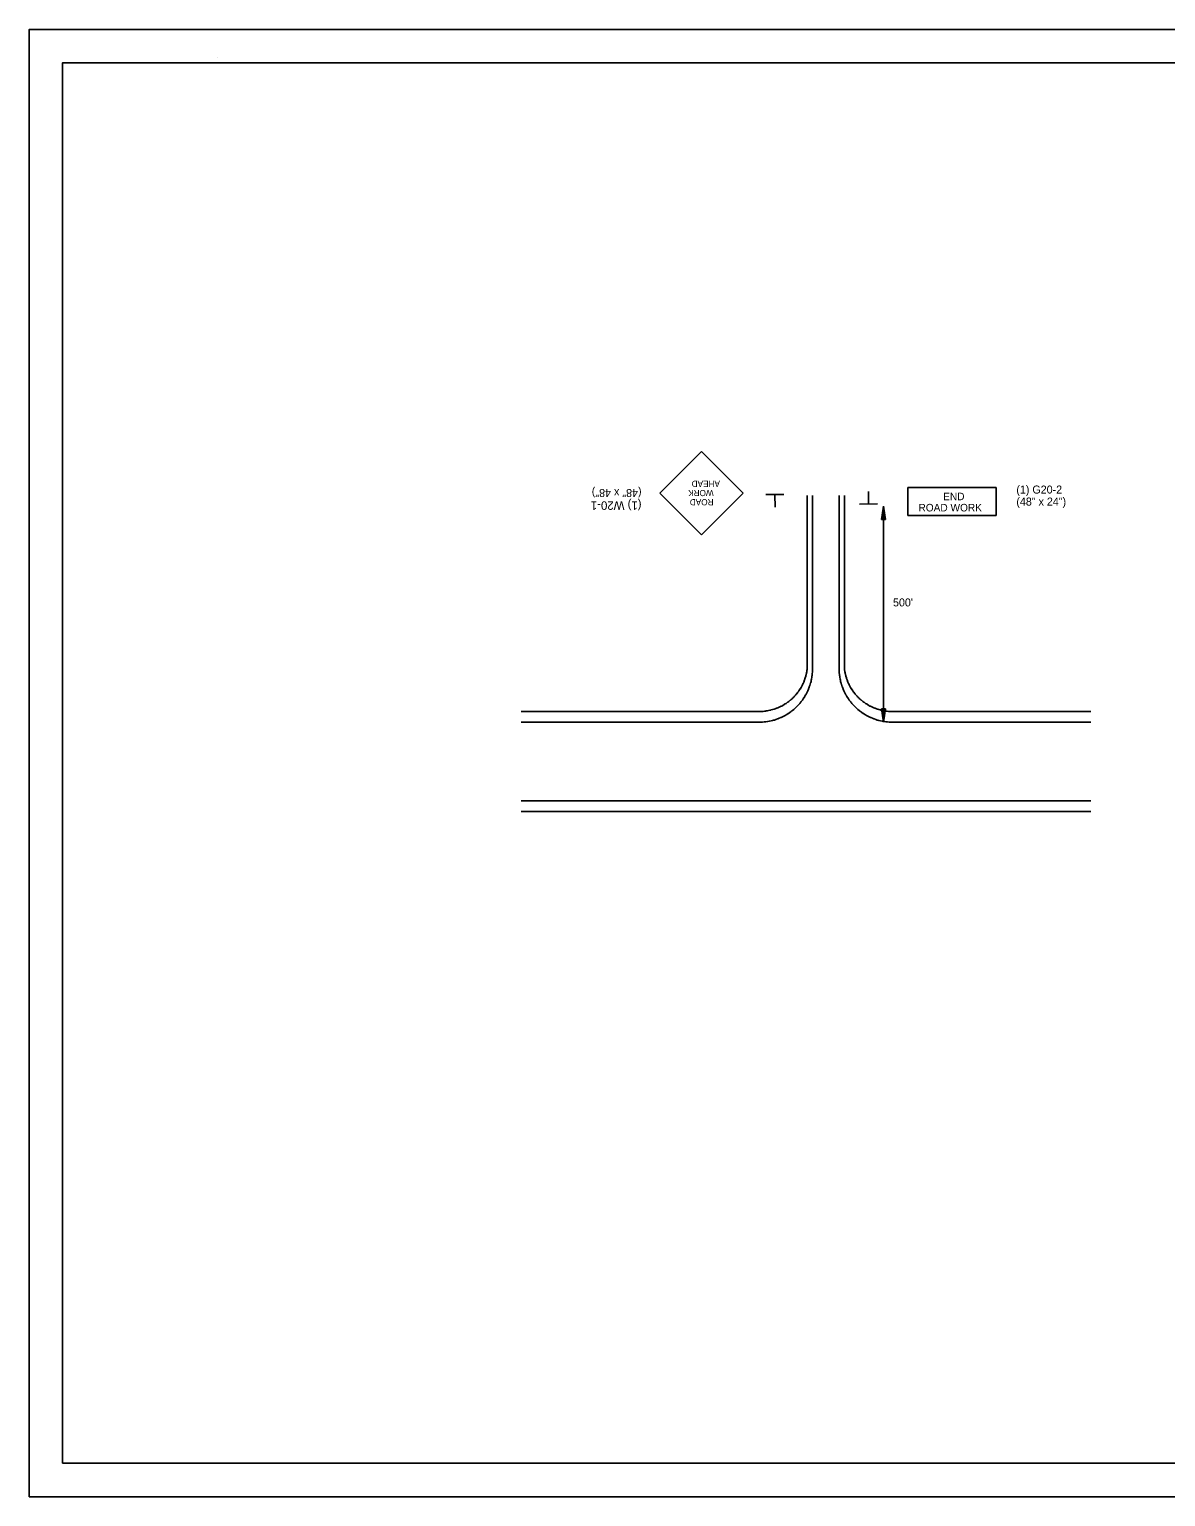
# Model space of a CAD drawing. Extents: x 32485 to 39285, y 55121 to 58033.
# Drawn here: x 32485 to 33337, y 56764 to 57864 of the extents above; entities that cross this region are included whole.
import ezdxf

# ---------------------------------------------------------------- set-up
doc = ezdxf.new("R2010")
doc.units = 0
doc.layers.add('Default', color=7, linetype='Continuous')
doc.layers.add('R_Border Notes', color=7, linetype='Continuous')

msp = doc.modelspace()

# ---------------------------------------------------------------- linework, layer by layer
at = {"layer": 'Default'}
for p, q in [((32957.9, 57516.2), (32989.2, 57547.4)), ((32989.2, 57547.4), (33020.5, 57516.2)), ((33210.2, 57520.4), (33143.8, 57520.4)), ((33143.8, 57499.5), (33143.8, 57520.4)), ((33210.2, 57499.5), (33210.2, 57520.4)), ((32957.9, 57516.2), (32989.2, 57484.9)), ((32989.2, 57484.9), (33020.5, 57516.2)), ((33037.5, 57515.1), (33051, 57515.3)), ((33044.2, 57515), (33044.4, 57505.8)), ((33068.4, 57476), (33068.4, 57514.5)), ((33072.4, 57476), (33072.4, 57514.5)), ((33092.4, 57476), (33092.4, 57514.5)), ((33096.4, 57476), (33096.4, 57514.5)), ((33121.1, 57508.1), (33107.6, 57508)), ((33114.3, 57508.3), (33114.3, 57517.5)), ((33124.2, 57496.4), (33125.7, 57506.4)), ((33124.5, 57496.4), (33125.7, 57504.7)), ((33124.7, 57496.4), (33125.7, 57503)), ((33125, 57496.4), (33125.7, 57501.4)), ((33125.2, 57496.4), (33125.7, 57499.7)), ((33125.5, 57496.4), (33125.7, 57498)), ((33125.7, 57506.4), (33125.7, 57344.5)), ((33127.2, 57496.4), (33125.7, 57506.4)), ((33127, 57496.4), (33125.7, 57504.7)), ((33126.7, 57496.4), (33125.7, 57503)), ((33126.4, 57496.4), (33125.7, 57501.4)), ((33126.2, 57496.4), (33125.7, 57499.7)), ((33125.9, 57496.4), (33125.7, 57498)), ((33210.2, 57499.5), (33143.8, 57499.5)), ((33124.2, 57496.4), (33127.2, 57496.4)), ((33124.2, 57354.5), (33125.7, 57344.5)), ((33124.2, 57354.5), (33127.2, 57354.5)), ((33124.5, 57354.5), (33125.7, 57346.2)), ((33124.7, 57354.5), (33125.7, 57347.9)), ((33125, 57354.5), (33125.7, 57349.5)), ((33125.2, 57354.5), (33125.7, 57351.2)), ((33125.5, 57354.5), (33125.7, 57352.9)), ((33127.2, 57354.5), (33125.7, 57344.5)), ((33126.2, 57354.5), (33125.7, 57351.2)), ((33126.7, 57354.5), (33125.7, 57347.9)), ((33127, 57354.5), (33125.7, 57346.2)), ((33126.4, 57354.5), (33125.7, 57349.5)), ((33125.9, 57354.5), (33125.7, 57352.9))]:
    msp.add_line(p, q, dxfattribs=at)
msp.add_lwpolyline([(32485, 57863.9), (32485, 56763.9), (34185, 56763.9), (34185, 57863.9)], close=True, dxfattribs=at)
for points in [[(33032.4, 57344.5), (33033.7, 57344.5), (33035, 57344.6), (33036.2, 57344.7), (33037.5, 57344.8), (33038.7, 57345), (33038.8, 57345), (33040, 57345.2), (33041.3, 57345.5), (33042.5, 57345.8), (33043.2, 57346), (33043.8, 57346.1), (33045, 57346.5), (33046.2, 57347), (33046.3, 57347), (33047.4, 57347.4), (33048.6, 57347.9), (33048.8, 57348), (33049.8, 57348.5), (33050.8, 57349), (33050.9, 57349), (33052, 57349.6), (33052.6, 57350), (33053.1, 57350.3), (33054.2, 57351), (33054.3, 57351), (33055.3, 57351.7), (33055.7, 57352), (33056.3, 57352.4), (33057, 57353), (33057.3, 57353.2), (33058.3, 57354), (33058.3, 57354), (33059.3, 57354.9), (33059.4, 57355), (33060.2, 57355.8), (33060.5, 57356), (33060.7, 57356.2), (33061.1, 57356.7), (33061.4, 57357), (33062, 57357.6), (33062.4, 57358), (33062.9, 57358.6), (33063.2, 57359), (33063.7, 57359.6), (33064, 57360), (33064.5, 57360.6), (33064.8, 57361), (33065.2, 57361.6), (33065.5, 57362), (33065.9, 57362.7), (33066.1, 57363), (33066.6, 57363.8), (33066.7, 57364), (33067, 57364.5), (33067.2, 57364.9), (33067.3, 57365), (33067.9, 57366), (33067.9, 57366), (33068.4, 57367), (33068.4, 57367.1), (33068.8, 57368), (33069, 57368.3), (33069.3, 57369), (33069.5, 57369.5), (33069.7, 57370), (33069.9, 57370.7), (33070, 57371), (33070.4, 57371.9), (33070.4, 57372), (33070.7, 57373), (33070.7, 57373.1), (33071, 57374), (33071.1, 57374.3), (33071.3, 57375), (33071.4, 57375.6), (33071.5, 57376), (33071.7, 57376.8), (33071.7, 57377), (33071.9, 57378), (33071.9, 57378.1), (33072, 57379), (33072.1, 57379.4), (33072.1, 57380), (33072.2, 57380.7), (33072.2, 57381), (33072.3, 57381.9), (33072.3, 57382), (33072.4, 57383), (33072.4, 57383.2), (33072.4, 57384), (33072.4, 57384.5), (33072.4, 57385), (33072.4, 57386), (33072.4, 57387), (33072.4, 57388), (33072.4, 57389), (33072.4, 57390), (33072.4, 57391), (33072.4, 57392), (33072.4, 57393), (33072.4, 57394), (33072.4, 57395), (33072.4, 57396), (33072.4, 57397), (33072.4, 57398), (33072.4, 57399), (33072.4, 57400), (33072.4, 57401), (33072.4, 57402), (33072.4, 57403), (33072.4, 57404), (33072.4, 57405), (33072.4, 57406), (33072.4, 57407), (33072.4, 57408), (33072.4, 57409), (33072.4, 57410), (33072.4, 57411), (33072.4, 57412), (33072.4, 57413), (33072.4, 57414), (33072.4, 57415), (33072.4, 57416), (33072.4, 57417), (33072.4, 57418), (33072.4, 57419), (33072.4, 57420), (33072.4, 57421), (33072.4, 57422), (33072.4, 57423), (33072.4, 57424), (33072.4, 57425), (33072.4, 57426), (33072.4, 57427), (33072.4, 57428), (33072.4, 57429), (33072.4, 57430), (33072.4, 57431), (33072.4, 57432), (33072.4, 57433), (33072.4, 57434), (33072.4, 57435), (33072.4, 57436), (33072.4, 57437), (33072.4, 57438), (33072.4, 57439), (33072.4, 57440), (33072.4, 57441), (33072.4, 57442), (33072.4, 57443), (33072.4, 57444), (33072.4, 57445), (33072.4, 57446), (33072.4, 57447), (33072.4, 57448), (33072.4, 57449), (33072.4, 57450), (33072.4, 57451), (33072.4, 57452), (33072.4, 57453), (33072.4, 57454), (33072.4, 57455), (33072.4, 57456), (33072.4, 57457), (33072.4, 57458), (33072.4, 57459), (33072.4, 57460), (33072.4, 57461), (33072.4, 57462), (33072.4, 57463), (33072.4, 57464), (33072.4, 57464.5), (33072.4, 57465), (33072.4, 57466), (33072.4, 57467), (33072.4, 57468), (33072.4, 57469), (33072.4, 57470), (33072.4, 57471), (33072.4, 57472), (33072.4, 57473), (33072.4, 57473.7), (33072.4, 57474), (33072.4, 57475), (33072.4, 57476)], [(33032.4, 57352.5), (33033.4, 57352.5), (33034.4, 57352.5), (33035.5, 57352.6), (33036.5, 57352.7), (33037.4, 57352.8), (33037.5, 57352.9), (33038.5, 57353), (33039.5, 57353.2), (33040.5, 57353.4), (33041.1, 57353.5), (33041.5, 57353.7), (33042.5, 57353.9), (33043.5, 57354.2), (33043.6, 57354.3), (33044.5, 57354.6), (33045.5, 57354.9), (33045.6, 57355), (33046.5, 57355.3), (33047.3, 57355.7), (33047.4, 57355.7), (33048.4, 57356.2), (33048.9, 57356.4), (33049.3, 57356.6), (33050.2, 57357.1), (33050.2, 57357.1), (33051.1, 57357.7), (33051.5, 57357.9), (33052, 57358.2), (33052.6, 57358.6), (33052.9, 57358.8), (33053.7, 57359.4), (33053.8, 57359.4), (33054.6, 57360), (33054.7, 57360.1), (33055.4, 57360.7), (33055.7, 57360.9), (33055.9, 57361), (33056.3, 57361.4), (33056.5, 57361.6), (33057.1, 57362.1), (33057.4, 57362.4), (33057.8, 57362.8), (33058.2, 57363.2), (33058.6, 57363.6), (33058.9, 57363.9), (33059.3, 57364.4), (33059.6, 57364.7), (33060, 57365.2), (33060.3, 57365.5), (33060.7, 57366), (33060.9, 57366.3), (33061.4, 57366.9), (33061.5, 57367.1), (33061.8, 57367.5), (33062.1, 57367.8), (33062.1, 57367.9), (33062.7, 57368.7), (33062.7, 57368.7), (33063.2, 57369.5), (33063.3, 57369.6), (33063.7, 57370.3), (33063.8, 57370.6), (33064.2, 57371.1), (33064.4, 57371.5), (33064.6, 57372), (33064.9, 57372.5), (33065, 57372.8), (33065.4, 57373.5), (33065.4, 57373.6), (33065.8, 57374.5), (33065.8, 57374.6), (33066.1, 57375.3), (33066.2, 57375.6), (33066.4, 57376.2), (33066.6, 57376.7), (33066.7, 57377), (33067, 57377.8), (33067, 57377.9), (33067.3, 57378.7), (33067.3, 57378.8), (33067.5, 57379.6), (33067.6, 57380), (33067.7, 57380.5), (33067.8, 57381.1), (33067.9, 57381.4), (33068.1, 57382.2), (33068.1, 57382.3), (33068.2, 57383.1), (33068.2, 57383.3), (33068.3, 57384), (33068.4, 57384.5), (33068.4, 57385), (33068.4, 57386), (33068.4, 57387), (33068.4, 57388), (33068.4, 57389), (33068.4, 57390), (33068.4, 57391), (33068.4, 57392), (33068.4, 57393), (33068.4, 57394), (33068.4, 57395), (33068.4, 57396), (33068.4, 57397), (33068.4, 57398), (33068.4, 57399), (33068.4, 57400), (33068.4, 57401), (33068.4, 57402), (33068.4, 57403), (33068.4, 57404), (33068.4, 57405), (33068.4, 57406), (33068.4, 57407), (33068.4, 57408), (33068.4, 57409), (33068.4, 57410), (33068.4, 57411), (33068.4, 57412), (33068.4, 57413), (33068.4, 57414), (33068.4, 57415), (33068.4, 57416), (33068.4, 57417), (33068.4, 57418), (33068.4, 57419), (33068.4, 57420), (33068.4, 57421), (33068.4, 57422), (33068.4, 57423), (33068.4, 57424), (33068.4, 57425), (33068.4, 57426), (33068.4, 57427), (33068.4, 57428), (33068.4, 57429), (33068.4, 57430), (33068.4, 57431), (33068.4, 57432), (33068.4, 57433), (33068.4, 57434), (33068.4, 57435), (33068.4, 57436), (33068.4, 57437), (33068.4, 57438), (33068.4, 57439), (33068.4, 57440), (33068.4, 57441), (33068.4, 57442), (33068.4, 57443), (33068.4, 57444), (33068.4, 57445), (33068.4, 57446), (33068.4, 57447), (33068.4, 57448), (33068.4, 57449), (33068.4, 57450), (33068.4, 57451), (33068.4, 57452), (33068.4, 57453), (33068.4, 57454), (33068.4, 57455), (33068.4, 57456), (33068.4, 57457), (33068.4, 57458), (33068.4, 57459), (33068.4, 57460), (33068.4, 57461), (33068.4, 57462), (33068.4, 57463), (33068.4, 57464), (33068.4, 57464.5), (33068.4, 57465), (33068.4, 57466), (33068.4, 57467), (33068.4, 57468), (33068.4, 57469), (33068.4, 57470), (33068.4, 57471), (33068.4, 57472), (33068.4, 57473), (33068.4, 57473.7), (33068.4, 57474), (33068.4, 57475), (33068.4, 57476)], [(33132.4, 57344.5), (33131.1, 57344.5), (33129.8, 57344.6), (33128.6, 57344.7), (33127.3, 57344.8), (33126.1, 57345), (33126, 57345), (33124.7, 57345.2), (33123.5, 57345.5), (33122.2, 57345.8), (33121.5, 57346), (33121, 57346.1), (33119.8, 57346.5), (33118.6, 57347), (33118.5, 57347), (33117.4, 57347.4), (33116.2, 57347.9), (33116, 57348), (33115, 57348.5), (33114, 57349), (33113.9, 57349), (33112.8, 57349.6), (33112.2, 57350), (33111.7, 57350.3), (33110.6, 57351), (33110.5, 57351), (33109.5, 57351.7), (33109.1, 57352), (33108.5, 57352.4), (33107.7, 57353), (33107.5, 57353.2), (33106.5, 57354), (33106.5, 57354), (33105.5, 57354.9), (33105.4, 57355), (33104.6, 57355.8), (33104.3, 57356), (33104.1, 57356.2), (33103.7, 57356.7), (33103.3, 57357), (33102.8, 57357.6), (33102.4, 57358), (33101.9, 57358.6), (33101.6, 57359), (33101.1, 57359.6), (33100.8, 57360), (33100.3, 57360.6), (33100, 57361), (33099.6, 57361.6), (33099.3, 57362), (33098.9, 57362.7), (33098.7, 57363), (33098.2, 57363.8), (33098, 57364), (33097.8, 57364.5), (33097.5, 57364.9), (33097.5, 57365), (33096.9, 57366), (33096.9, 57366), (33096.4, 57367), (33096.4, 57367.1), (33096, 57368), (33095.8, 57368.3), (33095.5, 57369), (33095.3, 57369.5), (33095.1, 57370), (33094.9, 57370.7), (33094.7, 57371), (33094.4, 57371.9), (33094.4, 57372), (33094.1, 57373), (33094, 57373.1), (33093.8, 57374), (33093.7, 57374.3), (33093.5, 57375), (33093.4, 57375.6), (33093.3, 57376), (33093.1, 57376.8), (33093.1, 57377), (33092.9, 57378), (33092.9, 57378.1), (33092.8, 57379), (33092.7, 57379.4), (33092.6, 57380), (33092.6, 57380.7), (33092.5, 57381), (33092.5, 57381.9), (33092.5, 57382), (33092.4, 57383), (33092.4, 57383.2), (33092.4, 57384), (33092.4, 57384.5), (33092.4, 57385), (33092.4, 57386), (33092.4, 57387), (33092.4, 57388), (33092.4, 57389), (33092.4, 57390), (33092.4, 57391), (33092.4, 57392), (33092.4, 57393), (33092.4, 57394), (33092.4, 57395), (33092.4, 57396), (33092.4, 57397), (33092.4, 57398), (33092.4, 57399), (33092.4, 57400), (33092.4, 57401), (33092.4, 57402), (33092.4, 57403), (33092.4, 57404), (33092.4, 57405), (33092.4, 57406), (33092.4, 57407), (33092.4, 57408), (33092.4, 57409), (33092.4, 57410), (33092.4, 57411), (33092.4, 57412), (33092.4, 57413), (33092.4, 57414), (33092.4, 57415), (33092.4, 57416), (33092.4, 57417), (33092.4, 57418), (33092.4, 57419), (33092.4, 57420), (33092.4, 57421), (33092.4, 57422), (33092.4, 57423), (33092.4, 57424), (33092.4, 57425), (33092.4, 57426), (33092.4, 57427), (33092.4, 57428), (33092.4, 57429), (33092.4, 57430), (33092.4, 57431), (33092.4, 57432), (33092.4, 57433), (33092.4, 57434), (33092.4, 57435), (33092.4, 57436), (33092.4, 57437), (33092.4, 57438), (33092.4, 57439), (33092.4, 57440), (33092.4, 57441), (33092.4, 57442), (33092.4, 57443), (33092.4, 57444), (33092.4, 57445), (33092.4, 57446), (33092.4, 57447), (33092.4, 57448), (33092.4, 57449), (33092.4, 57450), (33092.4, 57451), (33092.4, 57452), (33092.4, 57453), (33092.4, 57454), (33092.4, 57455), (33092.4, 57456), (33092.4, 57457), (33092.4, 57458), (33092.4, 57459), (33092.4, 57460), (33092.4, 57461), (33092.4, 57462), (33092.4, 57463), (33092.4, 57464), (33092.4, 57464.5), (33092.4, 57465), (33092.4, 57466), (33092.4, 57467), (33092.4, 57468), (33092.4, 57469), (33092.4, 57470), (33092.4, 57471), (33092.4, 57472), (33092.4, 57473), (33092.4, 57473.7), (33092.4, 57474), (33092.4, 57475), (33092.4, 57476)], [(33132.4, 57352.5), (33131.4, 57352.5), (33130.3, 57352.5), (33129.3, 57352.6), (33128.3, 57352.7), (33127.3, 57352.8), (33127.3, 57352.9), (33126.3, 57353), (33125.3, 57353.2), (33124.2, 57353.4), (33123.7, 57353.5), (33123.2, 57353.7), (33122.2, 57353.9), (33121.3, 57354.2), (33121.2, 57354.3), (33120.3, 57354.6), (33119.3, 57354.9), (33119.2, 57355), (33118.3, 57355.3), (33117.4, 57355.7), (33117.4, 57355.7), (33116.4, 57356.2), (33115.9, 57356.4), (33115.5, 57356.6), (33114.6, 57357.1), (33114.6, 57357.1), (33113.7, 57357.7), (33113.3, 57357.9), (33112.8, 57358.2), (33112.1, 57358.6), (33111.9, 57358.8), (33111.1, 57359.4), (33111, 57359.4), (33110.2, 57360), (33110.1, 57360.1), (33109.4, 57360.7), (33109.1, 57360.9), (33108.9, 57361), (33108.5, 57361.4), (33108.3, 57361.6), (33107.7, 57362.1), (33107.4, 57362.4), (33107, 57362.8), (33106.6, 57363.2), (33106.2, 57363.6), (33105.9, 57363.9), (33105.5, 57364.4), (33105.2, 57364.7), (33104.7, 57365.2), (33104.5, 57365.5), (33104.1, 57366), (33103.9, 57366.3), (33103.4, 57366.9), (33103.2, 57367.1), (33103, 57367.5), (33102.7, 57367.8), (33102.7, 57367.9), (33102.1, 57368.7), (33102.1, 57368.7), (33101.6, 57369.5), (33101.5, 57369.6), (33101.1, 57370.3), (33101, 57370.6), (33100.6, 57371.1), (33100.4, 57371.5), (33100.2, 57372), (33099.9, 57372.5), (33099.8, 57372.8), (33099.4, 57373.5), (33099.4, 57373.6), (33099, 57374.5), (33099, 57374.6), (33098.7, 57375.3), (33098.6, 57375.6), (33098.3, 57376.2), (33098.2, 57376.7), (33098, 57377), (33097.8, 57377.8), (33097.8, 57377.9), (33097.5, 57378.7), (33097.5, 57378.8), (33097.3, 57379.6), (33097.2, 57380), (33097.1, 57380.5), (33096.9, 57381.1), (33096.9, 57381.4), (33096.7, 57382.2), (33096.7, 57382.3), (33096.6, 57383.1), (33096.5, 57383.3), (33096.4, 57384), (33096.4, 57384.5), (33096.4, 57385), (33096.4, 57386), (33096.4, 57387), (33096.4, 57388), (33096.4, 57389), (33096.4, 57390), (33096.4, 57391), (33096.4, 57392), (33096.4, 57393), (33096.4, 57394), (33096.4, 57395), (33096.4, 57396), (33096.4, 57397), (33096.4, 57398), (33096.4, 57399), (33096.4, 57400), (33096.4, 57401), (33096.4, 57402), (33096.4, 57403), (33096.4, 57404), (33096.4, 57405), (33096.4, 57406), (33096.4, 57407), (33096.4, 57408), (33096.4, 57409), (33096.4, 57410), (33096.4, 57411), (33096.4, 57412), (33096.4, 57413), (33096.4, 57414), (33096.4, 57415), (33096.4, 57416), (33096.4, 57417), (33096.4, 57418), (33096.4, 57419), (33096.4, 57420), (33096.4, 57421), (33096.4, 57422), (33096.4, 57423), (33096.4, 57424), (33096.4, 57425), (33096.4, 57426), (33096.4, 57427), (33096.4, 57428), (33096.4, 57429), (33096.4, 57430), (33096.4, 57431), (33096.4, 57432), (33096.4, 57433), (33096.4, 57434), (33096.4, 57435), (33096.4, 57436), (33096.4, 57437), (33096.4, 57438), (33096.4, 57439), (33096.4, 57440), (33096.4, 57441), (33096.4, 57442), (33096.4, 57443), (33096.4, 57444), (33096.4, 57445), (33096.4, 57446), (33096.4, 57447), (33096.4, 57448), (33096.4, 57449), (33096.4, 57450), (33096.4, 57451), (33096.4, 57452), (33096.4, 57453), (33096.4, 57454), (33096.4, 57455), (33096.4, 57456), (33096.4, 57457), (33096.4, 57458), (33096.4, 57459), (33096.4, 57460), (33096.4, 57461), (33096.4, 57462), (33096.4, 57463), (33096.4, 57464), (33096.4, 57464.5), (33096.4, 57465), (33096.4, 57466), (33096.4, 57467), (33096.4, 57468), (33096.4, 57469), (33096.4, 57470), (33096.4, 57471), (33096.4, 57472), (33096.4, 57473), (33096.4, 57473.7), (33096.4, 57474), (33096.4, 57475), (33096.4, 57476), (33096.4, 57476)], [(33032.4, 57352.5), (33027.4, 57352.5), (33017.4, 57352.5), (33007.4, 57352.5), (32997.4, 57352.5), (32987.4, 57352.5), (32977.4, 57352.5), (32969.4, 57352.5), (32967.4, 57352.5), (32957.4, 57352.5), (32947.4, 57352.5), (32937.4, 57352.5), (32927.4, 57352.5), (32917.4, 57352.5), (32907.4, 57352.5), (32897.4, 57352.5), (32896.2, 57352.5), (32887.4, 57352.5), (32877.4, 57352.5), (32867.4, 57352.5), (32857.4, 57352.5), (32853.8, 57352.5)], [(33032.4, 57344.5), (33027.4, 57344.5), (33017.4, 57344.5), (33007.4, 57344.5), (32997.4, 57344.5), (32987.4, 57344.5), (32977.4, 57344.5), (32969.4, 57344.5), (32967.4, 57344.5), (32957.4, 57344.5), (32947.4, 57344.5), (32937.4, 57344.5), (32927.4, 57344.5), (32917.4, 57344.5), (32907.4, 57344.5), (32897.4, 57344.5), (32896.2, 57344.5), (32887.4, 57344.5), (32877.4, 57344.5), (32867.4, 57344.5), (32857.4, 57344.5), (32853.8, 57344.5)], [(33281.2, 57352.5), (33277.4, 57352.5), (33267.4, 57352.5), (33257.4, 57352.5), (33247.4, 57352.5), (33237.4, 57352.5), (33227.4, 57352.5), (33217.4, 57352.5), (33207.4, 57352.5), (33197.4, 57352.5), (33189.2, 57352.5), (33189.2, 57352.5), (33187.4, 57352.5), (33177.4, 57352.5), (33167.4, 57352.5), (33157.4, 57352.5), (33147.4, 57352.5), (33137.4, 57352.5), (33132.4, 57352.5)], [(33281.2, 57344.5), (33277.4, 57344.5), (33267.4, 57344.5), (33257.4, 57344.5), (33247.4, 57344.5), (33237.4, 57344.5), (33227.4, 57344.5), (33217.4, 57344.5), (33207.4, 57344.5), (33197.4, 57344.5), (33189.2, 57344.5), (33189.2, 57344.5), (33187.4, 57344.5), (33177.4, 57344.5), (33167.4, 57344.5), (33157.4, 57344.5), (33147.4, 57344.5), (33137.4, 57344.5), (33132.4, 57344.5)], [(33281.2, 57285.5), (33267.4, 57285.5), (33257.4, 57285.5), (33247.4, 57285.5), (33237.4, 57285.5), (33227.4, 57285.5), (33217.4, 57285.5), (33207.4, 57285.5), (33197.4, 57285.5), (33189.2, 57285.5), (33189.2, 57285.5), (33187.4, 57285.5), (33177.4, 57285.5), (33167.4, 57285.5), (33157.4, 57285.5), (33147.4, 57285.5), (33137.4, 57285.5), (33127.4, 57285.5), (33117.4, 57285.5), (33107.4, 57285.5), (33097.4, 57285.5), (33087.4, 57285.5), (33082.4, 57285.5), (33077.4, 57285.5), (33067.4, 57285.5), (33057.4, 57285.5), (33047.4, 57285.5), (33042.7, 57285.5), (33042.7, 57285.5), (33037.4, 57285.5), (33027.4, 57285.5), (33017.4, 57285.5), (33007.4, 57285.5), (32997.4, 57285.5), (32987.4, 57285.5), (32977.4, 57285.5), (32969.4, 57285.5), (32967.4, 57285.5), (32957.4, 57285.5), (32947.4, 57285.5), (32937.4, 57285.5), (32927.4, 57285.5), (32917.4, 57285.5), (32907.4, 57285.5), (32897.4, 57285.5), (32896.2, 57285.5), (32887.4, 57285.5), (32877.4, 57285.5), (32867.4, 57285.5), (32857.4, 57285.5), (32853.8, 57285.5)], [(33281.2, 57277.5), (33267.4, 57277.5), (33257.4, 57277.5), (33247.4, 57277.5), (33237.4, 57277.5), (33227.4, 57277.5), (33217.4, 57277.5), (33207.4, 57277.5), (33197.4, 57277.5), (33189.2, 57277.5), (33189.2, 57277.5), (33187.4, 57277.5), (33177.4, 57277.5), (33167.4, 57277.5), (33157.4, 57277.5), (33147.4, 57277.5), (33137.4, 57277.5), (33127.4, 57277.5), (33117.4, 57277.5), (33107.4, 57277.5), (33097.4, 57277.5), (33087.4, 57277.5), (33082.4, 57277.5), (33077.4, 57277.5), (33067.4, 57277.5), (33057.4, 57277.5), (33047.4, 57277.5), (33042.7, 57277.5), (33042.7, 57277.5), (33037.4, 57277.5), (33027.4, 57277.5), (33017.4, 57277.5), (33007.4, 57277.5), (32997.4, 57277.5), (32987.4, 57277.5), (32977.4, 57277.5), (32969.4, 57277.5), (32967.4, 57277.5), (32957.4, 57277.5), (32947.4, 57277.5), (32937.4, 57277.5), (32927.4, 57277.5), (32917.4, 57277.5), (32907.4, 57277.5), (32897.4, 57277.5), (32896.2, 57277.5), (32887.4, 57277.5), (32877.4, 57277.5), (32867.4, 57277.5), (32857.4, 57277.5), (32853.8, 57277.5)]]:
    msp.add_lwpolyline(points, dxfattribs=at)
at = {"layer": 'R_Border Notes'}
msp.add_line((32626.1, 57842.5), (32626.1, 57842.5), dxfattribs=at)
msp.add_line((32626.1, 57842.5), (32626.1, 57842.5), dxfattribs=at)
for points in [[(32485, 56763.9), (34185, 56763.9), (34185, 57863.9), (32485, 57863.9)], [(32510, 56788.9), (34160, 56788.9), (34160, 57838.9), (32510, 57838.9)]]:
    msp.add_lwpolyline(points, close=True, dxfattribs=at)

# ---------------------------------------------------------------- texts
at = {"layer": 'Default'}
for s, height, rotation, p in [('(48" x 48")', 5.999, 180, (32944.2, 57519.3)), (' AHEAD ', 4.61, 180.0006, (33004.7, 57525.5)), ('(1) W20-1', 6.4, 180, (32944.2, 57510.1)), ('WORK', 4.61, 180, (32998.3, 57518.6)), ('ROAD', 4.61, 180.0004, (32998.2, 57511.7))]:
    msp.add_text(s, height=height, rotation=rotation, dxfattribs=at).set_placement(p)
for s, height, p in [('(1) G20-2', 6, (33225.3, 57515.9)), ('ROAD WORK', 5.67, (33151.9, 57502.5)), ('END', 5.67, (33170.4, 57510.9)), ('(48" x 24")', 5.999, (33225.3, 57506.9)), ("500'", 6, (33132.8, 57431.3))]:
    msp.add_text(s, height=height, dxfattribs=at).set_placement(p)

doc.saveas('drawing.dxf')
